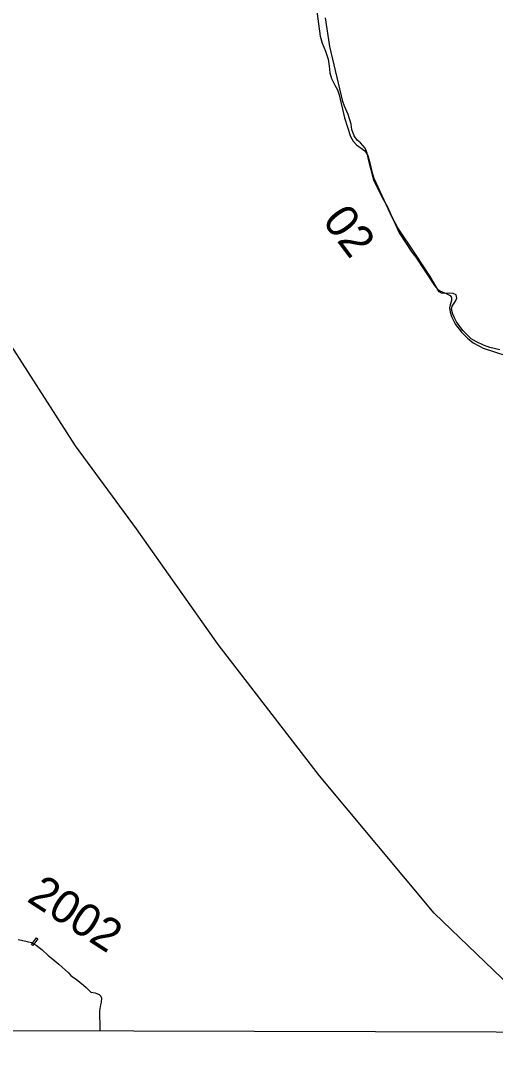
# Model space of a CAD drawing. Extents: x 3161564 to 3199464, y 849354 to 874788.
# Drawn here: x 3178273 to 3179471, y 854733 to 857334 of the extents above; entities that cross this region are included whole.
import ezdxf

# ---------------------------------------------------------------- set-up
doc = ezdxf.new("R2010")
doc.units = 0
for name, color, linetype in [('V-CHAN-DOCK', 7, 'Continuous'), ('V-GRID-FRAM', 7, 'Continuous'), ('V-RIVR-IDEN', 7, 'Continuous'), ('V-SITE-VEGE', 7, 'Continuous'), ('V-TOPO-BNDY', 7, 'Continuous'), ('V-TOPO-SHOR', 7, 'Continuous')]:
    doc.layers.add(name, color=color, linetype=linetype)

msp = doc.modelspace()

# ---------------------------------------------------------------- linework, layer by layer
at = {"layer": 'V-CHAN-DOCK'}
msp.add_lwpolyline([(3178300.6, 855002.9), (3178313.3, 855019.6), (3178316.8, 855016.9), (3178304.1, 855000.3), (3178300.6, 855002.9)], dxfattribs=at)
at = {"layer": 'V-GRID-FRAM'}
msp.add_lwpolyline([(3165819.2, 873007.6), (3197186.7, 872920.9), (3197144.3, 854733.3), (3165761, 854820), (3165819.2, 873007.6)], dxfattribs=at)
at = {"layer": 'V-SITE-VEGE'}
for p, q in [((3179018.5, 857369.2), (3179028.7, 857294.2)), ((3179028.7, 857294.2), (3179033.5, 857277)), ((3179033.5, 857277), (3179041.8, 857256.1)), ((3179041.8, 857256.1), (3179048.8, 857235.9)), ((3179048.8, 857235.9), (3179051.5, 857218.3)), ((3179051.5, 857218.3), (3179053, 857201.4)), ((3179053, 857201.4), (3179057.4, 857187.3)), ((3179057.4, 857187.3), (3179065.5, 857170.5)), ((3179065.5, 857170.5), (3179072.6, 857159.1)), ((3179072.6, 857159.1), (3179076.7, 857146.6)), ((3179076.7, 857146.6), (3179090.4, 857088.5)), ((3179090.4, 857088.5), (3179105.6, 857041.6)), ((3179105.6, 857041.6), (3179112.1, 857029.6)), ((3179112.1, 857029.6), (3179120.4, 857020.1)), ((3179120.4, 857020.1), (3179141.3, 857004.7)), ((3179141.3, 857004.7), (3179148.8, 856993.1)), ((3179148.8, 856993.1), (3179154.1, 856974.9)), ((3179154.1, 856974.9), (3179158.9, 856953)), ((3179158.9, 856953), (3179163.8, 856936.3)), ((3179163.8, 856936.3), (3179204.1, 856848.3)), ((3179204.1, 856848.3), (3179217.3, 856822.2)), ((3179217.3, 856822.2), (3179228, 856798.3)), ((3179228, 856798.3), (3179260.1, 856749.3)), ((3179260.1, 856749.3), (3179269.8, 856736.7)), ((3179269.8, 856736.7), (3179317.4, 856665.5)), ((3179317.4, 856665.5), (3179324.5, 856655.9)), ((3179324.5, 856655.9), (3179330.5, 856651.7)), ((3179330.5, 856651.7), (3179346.8, 856645)), ((3179346.8, 856645), (3179356.3, 856639.9)), ((3179356.3, 856639.9), (3179359.5, 856635.4)), ((3179359.7, 856627.6), (3179356.9, 856616.5)), ((3179359.5, 856635.4), (3179359.7, 856627.6)), ((3179356.9, 856616.5), (3179354.8, 856609)), ((3179354.8, 856609), (3179356.2, 856597.7)), ((3179356.2, 856597.7), (3179360, 856586.8)), ((3179360, 856586.8), (3179370, 856567)), ((3179370, 856567), (3179384.7, 856548)), ((3179384.7, 856548), (3179400.4, 856532.6)), ((3179400.4, 856532.6), (3179414.6, 856521)), ((3179414.6, 856521), (3179430.1, 856512.1)), ((3179430.1, 856512.1), (3179440, 856507.5)), ((3179440, 856507.5), (3179527.8, 856478.7))]:
    msp.add_line(p, q, dxfattribs=at)
at = {"layer": 'V-TOPO-BNDY'}
for p, q in [((3178412, 856261), (3178220.1, 856558.3)), ((3178566, 856051.6), (3178412, 856261)), ((3178771.4, 855760.1), (3178566, 856051.6)), ((3179027.1, 855428.4), (3178771.4, 855760.1)), ((3179316, 855081.8), (3179027.1, 855428.4)), ((3179622.7, 854787.1), (3179316, 855081.8))]:
    msp.add_line(p, q, dxfattribs=at)
at = {"layer": 'V-TOPO-SHOR'}
for points in [[(3179481.8, 856502.8), (3179456.6, 856509.1), (3179440.5, 856515.2), (3179422.6, 856523.5), (3179409.4, 856530.6), (3179388.7, 856551.7), (3179378.9, 856564.2), (3179372.9, 856573.4), (3179367.6, 856583.7), (3179363.5, 856593.3), (3179360, 856606), (3179361.6, 856613.4), (3179370.2, 856625.9), (3179373.6, 856633.2), (3179371.4, 856641.9), (3179364.1, 856645.4), (3179353.2, 856645.8), (3179343.5, 856645), (3179334.5, 856646.2), (3179328.6, 856649.4), (3179306.4, 856687.8), (3179269.4, 856744.1), (3179225, 856811.2), (3179211.3, 856836.4), (3179199.1, 856863.2), (3179185.9, 856886.4), (3179163.8, 856930.7), (3179151.2, 856980.1), (3179149.8, 856987.7), (3179147.5, 856999.2), (3179142.6, 857011.8), (3179130.5, 857025.2), (3179122.2, 857032.3), (3179114.7, 857042.9), (3179108.7, 857058.6), (3179107, 857072.2), (3179099.4, 857096.3), (3179090.4, 857117.8), (3179085.7, 857129.9), (3179053.5, 857268.1), (3179042.2, 857340.4)], [(3178267.3, 855015.2), (3178276, 855013.6), (3178300.8, 855007.9), (3178312.4, 855001.3), (3178320.5, 854995.7), (3178327, 854990.4), (3178342.7, 854974.9), (3178354.5, 854965.8), (3178370.1, 854953.2), (3178394, 854931.5), (3178399.7, 854924.8), (3178406.8, 854919.4), (3178413.2, 854915.1), (3178422.4, 854908.3), (3178432.2, 854900.5), (3178438.4, 854894.2)], [(3178438.4, 854894.2), (3178443.4, 854889.4), (3178450.7, 854883), (3178461.3, 854880.8), (3178465.6, 854879.3), (3178471.2, 854876.9), (3178475.6, 854872.2), (3178477.4, 854867.9), (3178476.6, 854857.5), (3178475, 854850.4), (3178472.2, 854835.8), (3178472.2, 854822.1), (3178473.1, 854802), (3178473.2, 854784.9)]]:
    msp.add_lwpolyline(points, dxfattribs=at)

# ---------------------------------------------------------------- texts
at = {"layer": 'V-RIVR-IDEN'}
for s, rotation, p in [('02', 306.861, (3179032.2, 856828.2)), ('2002', 327.1812, (3178286.3, 855113.4))]:
    msp.add_text(s, height=83, rotation=rotation, dxfattribs=at).set_placement(p)

doc.saveas('drawing.dxf')
